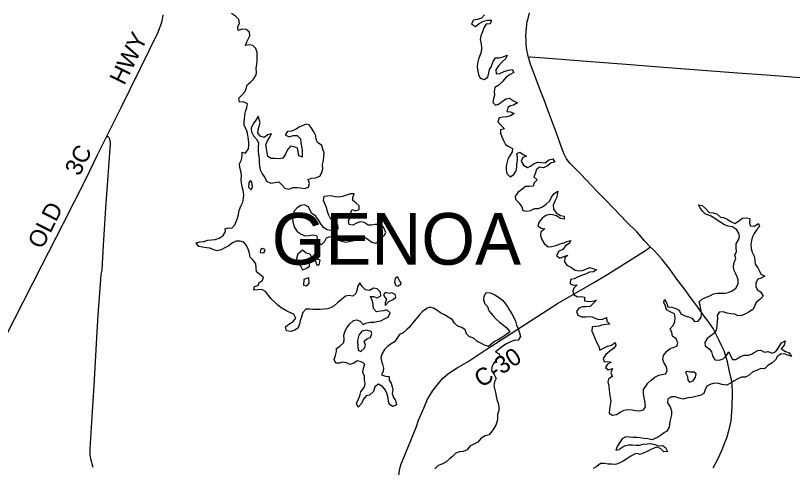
# Model space of a CAD drawing. Extents: x 1674899 to 2057726, y 653888 to 988278.
# Drawn here: x 1855438 to 1868981, y 790521 to 798397 of the extents above; entities that cross this region are included whole.
import ezdxf

# ---------------------------------------------------------------- set-up
doc = ezdxf.new("R2010")
doc.units = 0
for name, color, linetype in [('GM_X_County_Road', 7, 'Continuous'), ('GM_X_County_Road_Text', 7, 'Continuous'), ('GM_X_Major_Lake', 7, 'Continuous'), ('GM_X_Township_Text', 7, 'Continuous')]:
    doc.layers.add(name, color=color, linetype=linetype)

msp = doc.modelspace()

# ---------------------------------------------------------------- linework, layer by layer
at = {"layer": 'GM_X_County_Road'}
for points in [[(1857028, 796294), (1857277, 796797), (1857775, 797801), (1857924, 798107), (1857985, 798279), (1858004, 798364), (1858012, 798409)], [(1864668, 796879), (1864590, 797083), (1864513, 797287), (1864422, 797530), (1864380, 797664), (1864367, 797719), (1864351, 797802), (1864341, 797885), (1864336, 797962), (1864335, 798045), (1864343, 798179), (1864359, 798293), (1864372, 798348), (1864397, 798443)], [(1869596, 797271), (1869264, 797299), (1868606, 797350), (1867949, 797398), (1867262, 797449), (1866957, 797476), (1866512, 797510), (1866160, 797537), (1865389, 797594), (1864651, 797652), (1864490, 797665), (1864412, 797670), (1864397, 797669), (1864380, 797664)], [(1866503, 794368), (1866405, 794466), (1866272, 794620), (1866088, 794799), (1865870, 795027), (1865711, 795195), (1865579, 795328), (1865290, 795631), (1865178, 795747), (1865101, 795824), (1865042, 795902), (1865004, 795980), (1864969, 796070), (1864868, 796347), (1864745, 796675), (1864687, 796830), (1864668, 796879)], [(1851209, 784694), (1851326, 784936), (1852148, 786590), (1852443, 787187), (1853141, 788601), (1853675, 789667), (1853798, 789914), (1853979, 790280), (1854272, 790859), (1854392, 791103), (1854649, 791581), (1855260, 792799), (1855898, 794041), (1856273, 794777), (1856673, 795566), (1856869, 795971), (1857028, 796294)], [(1856946, 793960), (1856946, 793960), (1856971, 794394), (1857013, 795045), (1857051, 795598), (1857080, 796004), (1857092, 796153), (1857094, 796187), (1857090, 796216), (1857080, 796243), (1857067, 796263), (1857051, 796280), (1857028, 796294)], [(1862331, 790993), (1862331, 790993), (1862425, 791233), (1862464, 791347), (1862553, 791556), (1862621, 791712), (1862718, 791870), (1862878, 792073), (1862988, 792163), (1863137, 792257), (1863326, 792369), (1863622, 792566), (1863901, 792746), (1864887, 793380), (1865528, 793748), (1865763, 793892), (1866421, 794305), (1866453, 794326), (1866503, 794368)], [(1867241, 793436), (1867175, 793524), (1867110, 793619), (1866968, 793805), (1866845, 793974), (1866805, 794027), (1866710, 794146), (1866624, 794245), (1866569, 794300), (1866503, 794368)], [(1856789, 790519), (1856749, 790673), (1856741, 790738), (1856737, 790808), (1856738, 790844), (1856763, 791215), (1856781, 791498), (1856809, 791946), (1856855, 792786), (1856879, 793181), (1856895, 793405), (1856933, 793880), (1856936, 793913), (1856946, 793960)], [(1867596, 790512), (1867641, 790592), (1867690, 790690), (1867763, 790847), (1867804, 790955), (1867838, 791037), (1867877, 791180), (1867910, 791333), (1867929, 791569), (1867933, 791826), (1867927, 791967), (1867917, 792047), (1867886, 792196), (1867849, 792363), (1867813, 792478), (1867788, 792552), (1867745, 792648), (1867704, 792736), (1867647, 792848), (1867599, 792941), (1867524, 793055), (1867442, 793157), (1867330, 793312), (1867263, 793407), (1867241, 793436)], [(1862860, 787938), (1862891, 788070), (1862911, 788154), (1862924, 788278), (1862924, 788410), (1862919, 788484), (1862909, 788555), (1862881, 788678), (1862846, 788780), (1862782, 788915), (1862621, 789214), (1862525, 789400), (1862401, 789615), (1862280, 789828), (1862168, 790041), (1862129, 790158), (1862118, 790274), (1862114, 790336), (1862129, 790467), (1862155, 790566), (1862331, 790993)]]:
    msp.add_lwpolyline(points, dxfattribs=at)
at = {"layer": 'GM_X_Major_Lake'}
for points in [[(1859633, 797362), (1859639, 797406), (1859630, 797478), (1859642, 797546), (1859648, 797614), (1859651, 797684), (1859649, 797752), (1859628, 797822), (1859576, 797874), (1859510, 797888), (1859444, 797873), (1859471, 797939), (1859523, 798042), (1859514, 798105), (1859458, 798155), (1859388, 798157), (1859320, 798136), (1859311, 798202), (1859343, 798262), (1859329, 798328), (1859274, 798384), (1859200, 798430)], [(1863615, 798411), (1863559, 798349), (1863491, 798327), (1863423, 798318), (1863386, 798252), (1863456, 798207), (1863522, 798261), (1863594, 798297), (1863666, 798318), (1863732, 798314), (1863712, 798250), (1863642, 798246), (1863600, 798183), (1863575, 798111), (1863549, 798043), (1863536, 797977), (1863556, 797905), (1863563, 797833), (1863555, 797759), (1863531, 797699), (1863506, 797637), (1863492, 797569), (1863485, 797507), (1863491, 797455), (1863506, 797367), (1863536, 797307), (1863608, 797284), (1863668, 797326), (1863688, 797398), (1863701, 797458), (1863737, 797512)], [(1863737, 797512), (1863741, 797532), (1863761, 797598), (1863805, 797658), (1863871, 797661), (1863938, 797679), (1864008, 797707), (1863987, 797649), (1863923, 797591), (1863855, 797521), (1863808, 797449), (1863816, 797381), (1863882, 797387), (1863954, 797422), (1864026, 797446), (1864096, 797456), (1864124, 797403), (1864060, 797370), (1863993, 797326), (1863929, 797246), (1863865, 797182), (1863792, 797145), (1863780, 797075), (1863785, 797011), (1863769, 796945), (1863755, 796883), (1863806, 796834), (1863856, 796852), (1863921, 796902), (1863983, 796945), (1864051, 796957), (1864119, 796909), (1864185, 796878), (1864118, 796838), (1864068, 796823), (1864018, 796795), (1864004, 796725), (1864068, 796720), (1864130, 796692), (1864063, 796652), (1864003, 796629), (1863933, 796625), (1863869, 796617), (1863843, 796547), (1863904, 796483), (1863960, 796421), (1863894, 796403), (1863893, 796345), (1863915, 796285), (1863943, 796218), (1863978, 796152), (1864038, 796116), (1864100, 796081), (1864093, 796021), (1864049, 795949), (1864019, 795895), (1864008, 795845), (1863992, 795779), (1863988, 795709), (1864001, 795643), (1864057, 795589), (1864123, 795626), (1864163, 795690), (1864174, 795760), (1864178, 795812), (1864185, 795870), (1864187, 795926), (1864175, 795995), (1864227, 796018), (1864287, 795974), (1864345, 795947), (1864279, 795922), (1864254, 795858), (1864292, 795790), (1864360, 795749), (1864414, 795773), (1864478, 795818), (1864544, 795844), (1864608, 795834), (1864672, 795829), (1864735, 795883), (1864805, 795899), (1864840, 795844), (1864772, 795831), (1864710, 795775), (1864640, 795745), (1864572, 795754), (1864516, 795708), (1864501, 795658), (1864475, 795588), (1864531, 795534), (1864480, 795484), (1864458, 795422), (1864394, 795420), (1864328, 795417), (1864261, 795363), (1864195, 795311), (1864145, 795247), (1864150, 795197), (1864210, 795133), (1864264, 795064)], [(1859100, 794631), (1859092, 794681), (1859142, 794699), (1859208, 794692), (1859259, 794750), (1859283, 794810), (1859307, 794868), (1859324, 794932), (1859338, 795002), (1859364, 795072), (1859397, 795142), (1859409, 795212), (1859416, 795276), (1859404, 795346), (1859387, 795410), (1859375, 795482), (1859373, 795546), (1859376, 795596), (1859370, 795664), (1859347, 795748), (1859343, 795814), (1859376, 795880), (1859386, 795952), (1859386, 796018), (1859448, 796000), (1859497, 796074), (1859503, 796136), (1859505, 796192), (1859494, 796280), (1859484, 796346), (1859465, 796408), (1859425, 796478), (1859422, 796546), (1859426, 796598), (1859434, 796658), (1859449, 796722), (1859467, 796788), (1859484, 796856), (1859412, 796894), (1859340, 796885), (1859329, 796955), (1859383, 797009), (1859443, 797072), (1859459, 797124), (1859476, 797190), (1859534, 797236), (1859590, 797294), (1859633, 797362)], [(1859668, 796641), (1859624, 796571), (1859581, 796507), (1859545, 796436), (1859553, 796373), (1859588, 796303), (1859642, 796237), (1859671, 796173), (1859669, 796107), (1859668, 796037), (1859674, 795971), (1859685, 795905), (1859687, 795838), (1859691, 795772), (1859700, 795706), (1859736, 795638), (1859783, 795576), (1859815, 795512), (1859886, 795477), (1859958, 795485), (1860030, 795498), (1860078, 795446), (1860132, 795388), (1860201, 795369), (1860278, 795399), (1860345, 795399), (1860413, 795392), (1860477, 795380), (1860547, 795404), (1860560, 795472), (1860540, 795540), (1860598, 795565), (1860668, 795571), (1860740, 795597), (1860779, 795663), (1860795, 795724), (1860789, 795801), (1860808, 795868), (1860814, 795938), (1860815, 796005), (1860795, 796069), (1860776, 796135), (1860720, 796175)], [(1860720, 796175), (1860696, 796195), (1860678, 796245), (1860671, 796303), (1860635, 796370), (1860594, 796432), (1860554, 796492), (1860502, 796504), (1860436, 796477), (1860384, 796449), (1860316, 796409), (1860248, 796384), (1860176, 796378), (1860140, 796320), (1860209, 796286), (1860279, 796308), (1860347, 796307), (1860403, 796251), (1860410, 796185), (1860422, 796119), (1860432, 796055), (1860435, 795987), (1860437, 795927), (1860377, 795951), (1860363, 796025), (1860352, 796087), (1860292, 796111), (1860228, 796118), (1860170, 796050), (1860141, 795984), (1860097, 795914), (1860027, 795897), (1859959, 795905), (1859895, 795907), (1859833, 795942), (1859822, 796008), (1859814, 796082), (1859801, 796146), (1859827, 796212), (1859868, 796278), (1859902, 796338), (1859836, 796320), (1859772, 796274), (1859702, 796297), (1859660, 796351), (1859667, 796407), (1859685, 796467), (1859701, 796533), (1859668, 796641)], [(1859531, 795523), (1859505, 795483), (1859496, 795405), (1859544, 795357)], [(1859544, 795357), (1859568, 795411), (1859557, 795495), (1859531, 795523)], [(1861865, 794684), (1861849, 794706), (1861780, 794755), (1861708, 794757), (1861644, 794743), (1861582, 794744), (1861516, 794790), (1861450, 794802), (1861384, 794777), (1861316, 794743), (1861252, 794756), (1861239, 794820), (1861285, 794889), (1861284, 794965), (1861306, 795017), (1861372, 794995), (1861430, 795015), (1861430, 795079), (1861375, 795129), (1861319, 795171), (1861315, 795225), (1861340, 795291), (1861274, 795290), (1861206, 795264), (1861138, 795246), (1861074, 795229), (1861008, 795237), (1860940, 795253), (1860813, 795244)], [(1864264, 795064), (1864281, 795000), (1864349, 794986), (1864415, 794997), (1864485, 795033), (1864554, 795037), (1864624, 795064), (1864686, 795112), (1864750, 795170), (1864783, 795234), (1864829, 795297), (1864893, 795335), (1864881, 795281), (1864871, 795229), (1864836, 795163), (1864808, 795091), (1864813, 795025), (1864863, 794959), (1864937, 794912), (1865003, 794900), (1865002, 794850), (1864935, 794862), (1864869, 794905), (1864797, 794925), (1864745, 794929), (1864679, 794914), (1864615, 794868), (1864564, 794800), (1864542, 794734), (1864601, 794692), (1864663, 794677), (1864597, 794626), (1864591, 794565), (1864610, 794495), (1864654, 794425), (1864721, 794364), (1864786, 794374), (1864858, 794390), (1864930, 794419), (1864994, 794437), (1865046, 794461), (1865116, 794476), (1865088, 794424), (1865024, 794385), (1864977, 794317), (1864911, 794289), (1864869, 794213), (1864928, 794171), (1864997, 794198), (1865065, 794222), (1865012, 794172), (1865008, 794106), (1865048, 794044), (1865117, 794013)], [(1860813, 795244), (1860798, 795180), (1860825, 795130), (1860851, 795058), (1860864, 795006), (1860890, 794934), (1860925, 794867), (1860981, 794805), (1861051, 794751), (1861056, 794681), (1860998, 794641), (1860936, 794653), (1860870, 794664), (1860806, 794702), (1860757, 794766), (1860719, 794836), (1860668, 794905), (1860600, 794949), (1860571, 795001), (1860543, 795065), (1860477, 795096), (1860411, 795084), (1860345, 795047), (1860295, 794985), (1860264, 794909), (1860264, 794843), (1860278, 794779), (1860303, 794701), (1860347, 794632), (1860414, 794584), (1860482, 794560), (1860550, 794561), (1860620, 794573), (1860684, 794566), (1860703, 794496), (1860701, 794430), (1860769, 794406), (1860825, 794454), (1860857, 794523), (1860921, 794545), (1860985, 794517), (1861121, 794464), (1861192, 794450), (1861248, 794457), (1861312, 794473), (1861385, 794519), (1861451, 794544), (1861519, 794540), (1861586, 794496), (1861648, 794445), (1861712, 794431), (1861762, 794457), (1861810, 794520), (1861862, 794564), (1861893, 794618), (1861865, 794684)], [(1866427, 791939), (1866458, 791991), (1866518, 792043), (1866582, 792095), (1866652, 792129), (1866704, 792140), (1866772, 792154), (1866797, 792212), (1866783, 792272), (1866742, 792340), (1866722, 792405), (1866730, 792473), (1866783, 792539), (1866847, 792592), (1866903, 792612), (1866967, 792632), (1866984, 792694), (1866952, 792762), (1866888, 792811), (1866877, 792875), (1866851, 792937), (1866901, 792993), (1866930, 793057), (1866934, 793129), (1866923, 793201), (1866851, 793234), (1866785, 793268), (1866766, 793332), (1866740, 793395), (1866748, 793447), (1866792, 793380), (1866811, 793318), (1866879, 793312), (1866949, 793293), (1867007, 793261), (1867035, 793199), (1867103, 793162), (1867166, 793144), (1867228, 793123), (1867272, 793063), (1867338, 793069), (1867388, 793136), (1867393, 793206), (1867381, 793281), (1867370, 793341), (1867356, 793407), (1867414, 793457), (1867483, 793489), (1867553, 793516), (1867603, 793548), (1867675, 793558), (1867741, 793559), (1867809, 793561), (1867859, 793568), (1867929, 793602), (1867994, 793648), (1868036, 793724), (1868034, 793792), (1868015, 793844), (1867993, 793894), (1867959, 793963), (1867952, 794031), (1867966, 794095), (1867995, 794163), (1867977, 794223), (1868003, 794283), (1867998, 794347), (1868002, 794419), (1868043, 794489), (1868057, 794539), (1868045, 794605), (1868006, 794666), (1867934, 794712), (1867858, 794727), (1867798, 794751), (1867732, 794788), (1867667, 794830), (1867611, 794870), (1867551, 794905), (1867467, 794935), (1867414, 794986), (1867370, 795048), (1867344, 795100), (1867406, 795086), (1867468, 795028), (1867529, 794963), (1867599, 794961), (1867665, 794940), (1867727, 794884), (1867779, 794879), (1867843, 794851), (1867906, 794805), (1867976, 794772), (1868043, 794814), (1868111, 794868), (1868183, 794873), (1868237, 794859), (1868232, 794793), (1868246, 794732), (1868316, 794728), (1868390, 794770)], [(1868390, 794770), (1868408, 794720), (1868360, 794666), (1868315, 794600), (1868279, 794530), (1868269, 794476), (1868258, 794408), (1868262, 794338), (1868279, 794273), (1868315, 794205), (1868324, 794135), (1868332, 794063), (1868378, 793998), (1868409, 793940), (1868431, 793890), (1868497, 793857), (1868437, 793820), (1868378, 793804), (1868342, 793740), (1868342, 793674), (1868365, 793622), (1868431, 793577), (1868469, 793507), (1868412, 793447), (1868344, 793391), (1868318, 793327), (1868289, 793273), (1868225, 793232), (1868163, 793198), (1868099, 793168), (1868029, 793165), (1867975, 793193), (1867909, 793197), (1867841, 793212), (1867771, 793234), (1867703, 793229), (1867671, 793171), (1867672, 793117), (1867668, 793053), (1867662, 793000), (1867655, 792938), (1867631, 792872), (1867558, 792813), (1867492, 792767), (1867452, 792701), (1867461, 792641), (1867527, 792590), (1867567, 792538), (1867588, 792468), (1867630, 792399), (1867704, 792389), (1867774, 792415), (1867830, 792472), (1867873, 792534), (1867902, 792466), (1867936, 792400), (1867996, 792405), (1868066, 792447), (1868139, 792479), (1868213, 792480), (1868265, 792498), (1868315, 792522), (1868379, 792561), (1868431, 792563), (1868493, 792529), (1868549, 792542), (1868633, 792510), (1868693, 792544), (1868745, 792619), (1868788, 792691), (1868856, 792725), (1868838, 792655), (1868785, 792587), (1868857, 792543), (1868925, 792520), (1868965, 792456), (1868901, 792476), (1868837, 792499), (1868771, 792497), (1868712, 792449), (1868688, 792395), (1868626, 792345), (1868552, 792300), (1868491, 792242), (1868429, 792244), (1868355, 792209), (1868289, 792185), (1868227, 792131), (1868162, 792092), (1868094, 792096), (1868030, 792068), (1867966, 792031), (1867898, 791991), (1867837, 791953), (1867755, 791964), (1867690, 791986), (1867622, 791987), (1867555, 791971), (1867487, 791935), (1867451, 791861), (1867435, 791809)], [(1861685, 793054), (1861737, 793064), (1861805, 793079), (1861869, 793111), (1861933, 793141), (1861968, 793213), (1861908, 793267), (1861858, 793253), (1861794, 793242), (1861728, 793236), (1861677, 793290), (1861671, 793364), (1861652, 793431), (1861626, 793499), (1861678, 793500), (1861742, 793480), (1861804, 793514), (1861798, 793578), (1861741, 793632), (1861677, 793645), (1861609, 793605), (1861537, 793615), (1861481, 793674), (1861442, 793738), (1861401, 793674), (1861393, 793624), (1861367, 793550), (1861316, 793506), (1861251, 793519), (1861187, 793507), (1861118, 793449), (1861056, 793394), (1860992, 793336), (1860942, 793306), (1860879, 793287), (1860815, 793279), (1860746, 793271), (1860680, 793274), (1860618, 793276), (1860566, 793282), (1860496, 793279), (1860444, 793221), (1860421, 793147), (1860401, 793077), (1860388, 793025), (1860364, 792957), (1860304, 792913), (1860234, 792890), (1860162, 792902), (1860142, 792970), (1860203, 793018), (1860275, 793062), (1860323, 793125), (1860290, 793190), (1860222, 793220), (1860148, 793256), (1860078, 793297), (1860013, 793345), (1859961, 793394), (1859894, 793458), (1859848, 793520), (1859797, 793587), (1859731, 793625), (1859661, 793617), (1859589, 793610), (1859601, 793676), (1859667, 793691), (1859686, 793747), (1859736, 793773), (1859758, 793831), (1859695, 793885), (1859637, 793928), (1859633, 794002), (1859624, 794068), (1859578, 794134), (1859529, 794188), (1859515, 794254), (1859490, 794323), (1859464, 794389), (1859418, 794449), (1859355, 794467), (1859283, 794466), (1859217, 794436), (1859156, 794386), (1859088, 794347), (1859020, 794311), (1858954, 794294), (1858894, 794316), (1858824, 794340), (1858773, 794347), (1858699, 794359), (1858633, 794369), (1858585, 794434), (1858653, 794455), (1858721, 794461), (1858787, 794485), (1858851, 794486), (1858919, 794496), (1858989, 794519), (1859058, 794561), (1859100, 794631)], [(1859737, 794335), (1859705, 794314), (1859701, 794270), (1859737, 794261)], [(1859737, 794261), (1859773, 794269), (1859789, 794321), (1859737, 794335)], [(1860440, 794310), (1860356, 794236), (1860338, 794162), (1860347, 794096), (1860405, 794032), (1860438, 793967), (1860506, 793991), (1860561, 794029)], [(1860561, 794029), (1860561, 794073), (1860543, 794123), (1860601, 794183), (1860574, 794237), (1860506, 794253), (1860440, 794310)], [(1860730, 794052), (1860745, 794132), (1860701, 794152), (1860641, 794140)], [(1860641, 794140), (1860673, 794102), (1860686, 794050), (1860730, 794052)], [(1865117, 794013), (1865129, 794003), (1865191, 793961), (1865255, 793948), (1865315, 793952), (1865369, 793972), (1865441, 794003), (1865501, 793989), (1865563, 793967), (1865513, 793929), (1865441, 793923), (1865371, 793892), (1865303, 793866), (1865236, 793840), (1865174, 793811), (1865110, 793795), (1865104, 793719), (1865166, 793696), (1865230, 793704), (1865171, 793648), (1865153, 793598), (1865165, 793536), (1865232, 793496), (1865298, 793499), (1865358, 793487), (1865358, 793425), (1865424, 793414), (1865496, 793418), (1865566, 793436), (1865508, 793378), (1865453, 793326), (1865385, 793322), (1865321, 793319), (1865257, 793295), (1865215, 793241), (1865242, 793177), (1865312, 793144), (1865378, 793144), (1865430, 793150), (1865490, 793147), (1865556, 793117), (1865608, 793099), (1865674, 793108), (1865740, 793136), (1865746, 793068), (1865796, 793017), (1865729, 793014), (1865659, 793000), (1865605, 792982), (1865553, 792975), (1865487, 792969), (1865485, 792897), (1865512, 792833), (1865540, 792760), (1865572, 792692), (1865607, 792628), (1865623, 792565), (1865689, 792601), (1865757, 792637), (1865825, 792652), (1865888, 792698), (1865903, 792648), (1865863, 792594), (1865799, 792546), (1865728, 792489), (1865680, 792421), (1865700, 792363), (1865760, 792368), (1865820, 792356), (1865755, 792320), (1865719, 792264), (1865771, 792222), (1865843, 792244), (1865817, 792174), (1865836, 792105), (1865772, 792062), (1865762, 792012), (1865777, 791939), (1865785, 791877), (1865792, 791809), (1865802, 791741), (1865812, 791677), (1865801, 791606), (1865791, 791534), (1865788, 791466), (1865844, 791434), (1865916, 791441), (1865980, 791485), (1866047, 791519), (1866111, 791528), (1866185, 791524), (1866249, 791512), (1866317, 791507), (1866383, 791523), (1866417, 791579), (1866411, 791631), (1866408, 791683), (1866396, 791735), (1866384, 791807), (1866387, 791878), (1866427, 791939)], [(1860461, 793797), (1860455, 793697), (1860514, 793687), (1860557, 793735)], [(1860557, 793735), (1860553, 793827), (1860509, 793813), (1860461, 793797)], [(1862098, 793846), (1862053, 793817), (1862043, 793753), (1862065, 793690), (1862115, 793680), (1862125, 793706), (1862151, 793704), (1862157, 793740)], [(1862157, 793740), (1862135, 793770), (1862121, 793804), (1862098, 793846)], [(1862054, 793538), (1861996, 793563), (1861948, 793553), (1861882, 793571), (1861850, 793532), (1861876, 793489), (1861907, 793455)], [(1861907, 793455), (1861881, 793389), (1861883, 793345), (1861943, 793413), (1862019, 793449), (1862069, 793488), (1862054, 793538)], [(1863696, 793247), (1863671, 793318), (1863625, 793368), (1863601, 793434), (1863604, 793504), (1863644, 793568), (1863710, 793562)], [(1863710, 793562), (1863731, 793561), (1863794, 793530), (1863858, 793486), (1863924, 793437), (1863979, 793375), (1864021, 793312), (1864051, 793262), (1864090, 793196), (1864122, 793135), (1864150, 793071), (1864173, 793003), (1864197, 792939), (1864224, 792870), (1864238, 792804), (1864200, 792742), (1864128, 792731), (1864064, 792709), (1863997, 792675), (1863933, 792633), (1863871, 792584), (1863804, 792534), (1863868, 792502), (1863878, 792441), (1863818, 792394), (1863767, 792332), (1863739, 792268), (1863737, 792208), (1863782, 792143), (1863816, 792073), (1863789, 792013), (1863775, 791945), (1863793, 791875), (1863802, 791825), (1863816, 791762), (1863828, 791708), (1863853, 791642), (1863865, 791580), (1863860, 791512), (1863842, 791445), (1863838, 791379), (1863833, 791327), (1863811, 791259), (1863775, 791201), (1863693, 791092)], [(1863680, 792629), (1863610, 792655), (1863547, 792686), (1863481, 792720), (1863413, 792781), (1863350, 792799), (1863298, 792851), (1863278, 792921), (1863217, 792962), (1863147, 792982), (1863087, 793035), (1863046, 793099), (1862978, 793141), (1862914, 793178), (1862847, 793214), (1862783, 793264), (1862723, 793299), (1862660, 793315), (1862606, 793291), (1862533, 793240), (1862477, 793180), (1862423, 793110), (1862360, 793038), (1862306, 792965), (1862256, 792923), (1862193, 792865), (1862129, 792838), (1862087, 792768), (1862041, 792708), (1861988, 792676), (1861926, 792636), (1861868, 792575), (1861828, 792505), (1861803, 792437), (1861819, 792371), (1861832, 792321), (1861850, 792253), (1861844, 792199), (1861819, 792137), (1861889, 792112), (1861953, 792104), (1861950, 792042), (1861986, 791988), (1862002, 791925), (1862013, 791875), (1862005, 791807), (1862025, 791739), (1862060, 791689), (1862078, 791615), (1862014, 791583), (1861956, 791617), (1861938, 791670), (1861933, 791734), (1861917, 791800), (1861889, 791866), (1861832, 791932), (1861764, 791971), (1861702, 791925), (1861680, 791845), (1861609, 791783), (1861547, 791770), (1861497, 791708), (1861473, 791640), (1861408, 791570), (1861383, 791633), (1861413, 791702), (1861437, 791770), (1861456, 791840), (1861516, 791912), (1861533, 791978), (1861523, 792046), (1861519, 792114), (1861492, 792178), (1861506, 792252), (1861529, 792326), (1861465, 792361), (1861393, 792379), (1861335, 792339), (1861267, 792318), (1861205, 792346), (1861135, 792354), (1861083, 792341), (1861023, 792341), (1860994, 792403), (1861014, 792473), (1861033, 792541), (1861031, 792593), (1861089, 792635), (1861159, 792697), (1861166, 792753), (1861158, 792829), (1861185, 792901), (1861213, 792952), (1861259, 793018), (1861330, 793082), (1861382, 793094), (1861447, 793069), (1861495, 793011), (1861545, 793033), (1861617, 793054), (1861685, 793054)], [(1863696, 793247), (1863703, 793232), (1863758, 793168), (1863814, 793105), (1863877, 793045), (1863943, 793002), (1864005, 792946), (1864053, 792885), (1863982, 792832), (1863914, 792788), (1863850, 792744), (1863786, 792715), (1863680, 792629)], [(1861634, 792888), (1861564, 792911), (1861474, 792897), (1861424, 792827), (1861399, 792735), (1861405, 792625), (1861412, 792565), (1861456, 792539)], [(1861456, 792539), (1861520, 792599), (1861537, 792651), (1861515, 792721), (1861559, 792765), (1861626, 792788), (1861648, 792854), (1861634, 792888)], [(1867292, 792093), (1867303, 792155), (1867267, 792179), (1867193, 792180), (1867143, 792194), (1867119, 792178)], [(1867119, 792178), (1867150, 792106), (1867156, 792041), (1867188, 792007), (1867252, 792031), (1867292, 792093)], [(1867092, 791719), (1867074, 791711), (1867008, 791728), (1866940, 791754), (1866870, 791750), (1866808, 791715), (1866805, 791647), (1866849, 791576), (1866873, 791510), (1866872, 791440), (1866858, 791390), (1866842, 791322), (1866829, 791222), (1866791, 791154), (1866750, 791128)], [(1867435, 791809), (1867370, 791774), (1867296, 791756), (1867226, 791740), (1867158, 791733), (1867092, 791719)], [(1863693, 791092), (1863625, 791074), (1863556, 791034), (1863496, 790961), (1863428, 790927), (1863358, 790893), (1863309, 790828), (1863241, 790798), (1863179, 790794), (1863111, 790767), (1863057, 790713), (1863003, 790671), (1862938, 790613), (1862870, 790580), (1862802, 790556), (1862746, 790498)], [(1866750, 791128), (1866700, 791088), (1866648, 791054), (1866578, 791019), (1866528, 791003), (1866462, 791021), (1866388, 791028), (1866326, 791036), (1866274, 791040), (1866206, 791043), (1866138, 791047), (1866074, 791052), (1866010, 791020), (1865977, 790968), (1865933, 790896), (1865899, 790824), (1865955, 790832), (1866021, 790882), (1866071, 790901), (1866125, 790913), (1866191, 790917), (1866259, 790912), (1866313, 790912), (1866381, 790924), (1866449, 790933), (1866511, 790939), (1866581, 790922), (1866647, 790900), (1866713, 790906), (1866767, 790867), (1866800, 790799), (1866740, 790795), (1866683, 790854), (1866617, 790872), (1866551, 790854), (1866501, 790827), (1866446, 790799), (1866378, 790771), (1866328, 790749), (1866276, 790762), (1866226, 790752), (1866162, 790720), (1866094, 790673), (1866029, 790633), (1865961, 790597), (1865895, 790572), (1865829, 790578), (1865769, 790576), (1865703, 790589), (1865637, 790589), (1865573, 790537), (1865505, 790502)]]:
    msp.add_lwpolyline(points, dxfattribs=at)

# ---------------------------------------------------------------- texts
at = {"layer": 'GM_X_County_Road_Text'}
for s, rotation, p in [('HWY', 63.6902, (1857332, 797168)), ('3C', 63.1767, (1856549, 795585)), ('OLD', 63.1383, (1855902, 794310)), ('C-30', 33.1231, (1863558, 791902))]:
    msp.add_text(s, height=300, rotation=rotation, dxfattribs=at).set_placement(p)
at = {"layer": 'GM_X_Township_Text'}
msp.add_text('GENOA', height=900, rotation=0, dxfattribs=at).set_placement((1859903, 794055))

doc.saveas('drawing.dxf')
